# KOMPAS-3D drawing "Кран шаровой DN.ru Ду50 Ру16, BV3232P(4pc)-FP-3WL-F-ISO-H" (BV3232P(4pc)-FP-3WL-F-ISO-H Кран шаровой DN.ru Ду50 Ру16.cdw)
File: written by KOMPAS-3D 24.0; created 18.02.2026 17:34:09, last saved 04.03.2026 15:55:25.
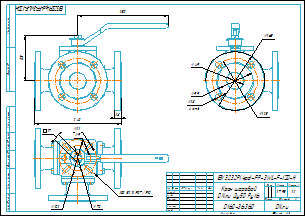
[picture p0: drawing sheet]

Document properties: Автор: R2D2; Форматы листов документа: A3; Полное имя файла: BV3232P(4pc)-FP-3WL-F-ISO-H Кран шаровой DN.ru Ду50 Ру16.m3d; Масса: 17.95; Наименование: Кран шаровой DN.ru Ду50 Ру16; Количество листов документа: 1; Примечание: D160-36360

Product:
- Part/product: Кран шаровой DN.ru Ду50 Ру16  | designation BV3232P(4pc)-FP-3WL-F-ISO-H
    Масса: 17.95
    Раздел спецификации: Прочие изделия
    Примечание: D160-36360

Views: Вид 1, Спереди, Проекционный вид 2
Referenced files in E:\Работа\Зайцев\BV3232P(4pc)-FP-3WL-F-ISO-H Кран шаровой DN.ru Ду15-100 Ру16\DN50\: BV3232P(4pc)-FP-3WL-F-ISO-H Кран шаровой DN.ru Ду50 Ру16.m3d
Referenced files in E:\Работа\Зайцев\Для компаса\: чертеж DN.ru А3.cdt
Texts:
  BV3232P(4pc)-FP-3WL-F-ISO-H
  чертеж DN.ru А3.cdt
  Кран шаровой
  DN.ru Ду50 Ру16
  Кран шаровой DN.ru Ду50 Ру16
  BV3232P(4pc)-FP-3WL-F-ISO-H Кран шаровой DN.ru Ду50 Ру16
Dimensions and other numbers on the sheet: 0; 3; 2; 4; 240; 18; 125; 250; 165; 99; 49; 4 отв.; 1:2; 1; 17,95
